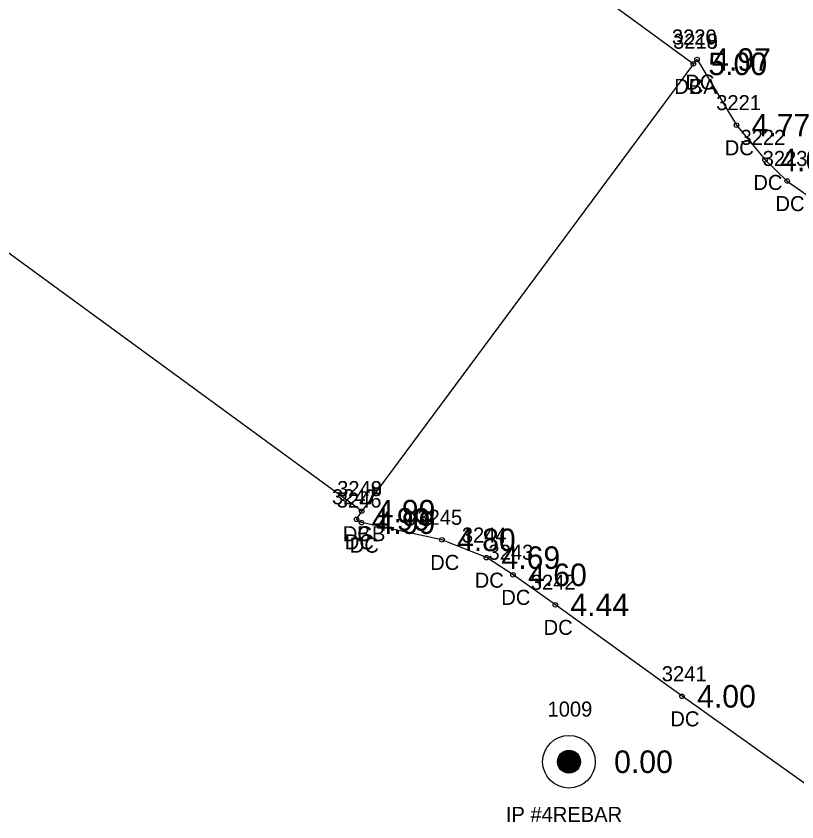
# Model space of a CAD drawing. Extents: x 2608598 to 2610682, y 641451 to 643526.
# Drawn here: x 2609915.7 to 2609967.6, y 641984.1 to 642037.7 of the extents above; entities that cross this region are included whole.
import ezdxf

# ---------------------------------------------------------------- set-up
doc = ezdxf.new("R2010")
doc.units = 0
for name, color, linetype in [('RD_EX_Bldg', 7, 'Continuous'), ('RD_EX_Bldg_txCode', 7, 'Continuous'), ('RD_EX_Conc', 7, 'Continuous'), ('RD_EX_Conc_txCode', 7, 'Continuous'), ('RD_EX_DV_Prop_txCode', 7, 'Continuous'), ('RD_EX_DV_PropPin', 7, 'Continuous'), ('RD_EX_TX_Bldg_ELEV', 7, 'Continuous'), ('RD_EX_TX_Conc_ELEV', 7, 'Continuous'), ('RD_EX_TX_DV_Prop_ELEV', 7, 'Continuous'), ('RD_SMD_Locator', 7, 'Continuous')]:
    doc.layers.add(name, color=color, linetype=linetype)

msp = doc.modelspace()

# ---------------------------------------------------------------- linework, layer by layer
at = {"layer": 'RD_EX_Bldg'}
msp.add_lwpolyline([(2609909.121, 642072.222), (2609960.739, 642034.485), (2609938.692, 642004.745), (2609887.073, 642042.482), (2609909.121, 642072.222)], dxfattribs=at)
at = {"layer": 'RD_EX_Conc'}
for points in [[(2609960.739, 642034.485), (2609960.987, 642034.768), (2609963.606, 642030.403), (2609965.507, 642028.097), (2609966.979, 642026.692), (2609972.604, 642022.767), (2609980.207, 642017.235), (2609987.972, 642011.523)], [(2609969.557, 641985.649), (2609959.989, 641992.436), (2609951.566, 641998.518), (2609948.754, 642000.513), (2609946.984, 642001.655), (2609944.027, 642002.836), (2609938.684, 642003.981), (2609938.35, 642004.199), (2609938.692, 642004.745)]]:
    msp.add_lwpolyline(points, dxfattribs=at)
at = {"layer": 'RD_EX_DV_PropPin'}
for p, q in [((2609951.842, 641987.66), (2609951.842, 641988.513)), ((2609951.877, 641987.612), (2609951.877, 641988.56)), ((2609951.912, 641987.571), (2609951.912, 641988.601)), ((2609951.947, 641987.536), (2609951.947, 641988.637)), ((2609951.982, 641987.504), (2609951.982, 641988.668)), ((2609952.017, 641987.476), (2609952.017, 641988.696)), ((2609952.052, 641987.452), (2609952.052, 641988.721)), ((2609952.087, 641987.43), (2609952.087, 641988.743)), ((2609952.122, 641987.411), (2609952.122, 641988.762)), ((2609952.157, 641987.394), (2609952.157, 641988.779)), ((2609952.192, 641987.379), (2609952.192, 641988.794)), ((2609952.227, 641987.366), (2609952.227, 641988.807)), ((2609952.262, 641987.355), (2609952.262, 641988.818)), ((2609952.297, 641987.346), (2609952.297, 641988.827)), ((2609952.332, 641987.338), (2609952.332, 641988.834)), ((2609952.367, 641987.333), (2609952.367, 641988.84)), ((2609952.402, 641987.329), (2609952.402, 641988.844)), ((2609952.437, 641987.326), (2609952.437, 641988.847)), ((2609952.472, 641987.325), (2609952.472, 641988.847)), ((2609952.507, 641987.326), (2609952.507, 641988.847)), ((2609952.542, 641987.329), (2609952.542, 641988.844)), ((2609952.577, 641987.333), (2609952.577, 641988.84)), ((2609952.612, 641987.338), (2609952.612, 641988.834)), ((2609952.647, 641987.346), (2609952.647, 641988.827)), ((2609952.682, 641987.355), (2609952.682, 641988.818)), ((2609952.717, 641987.366), (2609952.717, 641988.807)), ((2609952.752, 641987.379), (2609952.752, 641988.794)), ((2609952.787, 641987.394), (2609952.787, 641988.779)), ((2609952.822, 641987.411), (2609952.822, 641988.762)), ((2609952.857, 641987.43), (2609952.857, 641988.743)), ((2609952.892, 641987.452), (2609952.892, 641988.721)), ((2609952.927, 641987.476), (2609952.927, 641988.696)), ((2609952.962, 641987.504), (2609952.962, 641988.668)), ((2609952.997, 641987.536), (2609952.997, 641988.637)), ((2609953.032, 641987.571), (2609953.032, 641988.601)), ((2609953.067, 641987.612), (2609953.067, 641988.56)), ((2609953.102, 641987.66), (2609953.102, 641988.513)), ((2609951.737, 641987.89), (2609951.737, 641988.282)), ((2609951.772, 641987.788), (2609951.772, 641988.384)), ((2609951.807, 641987.717), (2609951.807, 641988.456)), ((2609953.137, 641987.717), (2609953.137, 641988.456)), ((2609953.172, 641987.788), (2609953.172, 641988.384)), ((2609953.207, 641987.89), (2609953.207, 641988.282))]:
    msp.add_line(p, q, dxfattribs=at)
for radius in [1.75, 0.761]:
    msp.add_circle((2609952.472, 641988.086), radius, dxfattribs=at)
at = {"layer": 'RD_SMD_Locator'}
for centre in [(2609960.739, 642034.485), (2609960.739, 642034.485), (2609960.987, 642034.768), (2609963.606, 642030.403), (2609965.507, 642028.097), (2609966.979, 642026.692), (2609938.692, 642004.745), (2609938.692, 642004.745), (2609938.35, 642004.199), (2609938.684, 642003.981), (2609944.027, 642002.836), (2609946.984, 642001.655), (2609948.754, 642000.513), (2609951.566, 641998.518), (2609959.989, 641992.436), (2609952.472, 641988.086)]:
    msp.add_circle(centre, 0.15, dxfattribs=at)

# ---------------------------------------------------------------- texts
at = {"layer": 'RD_EX_Bldg_txCode'}
for s, p in [('3218', (2609959.393, 642035.485)), ('B', (2609960.432, 642032.485)), ('3249', (2609937.062, 642005.745)), ('B', (2609938.384, 642002.745))]:
    msp.add_text(s, height=1, dxfattribs=at).set_placement(p)
at = {"layer": 'RD_EX_Conc_txCode'}
for s, p in [('3220', (2609959.318, 642035.768)), ('3219', (2609959.393, 642035.485)), ('DCA', (2609959.472, 642032.485)), ('DC', (2609960.207, 642032.768)), ('3221', (2609962.259, 642031.403)), ('3222', (2609963.877, 642029.097)), ('DC', (2609962.826, 642028.403)), ('3223', (2609965.349, 642027.692)), ('DC', (2609964.728, 642026.097)), ('DC', (2609966.2, 642024.692)), ('3248', (2609937.062, 642005.745)), ('3247', (2609936.72, 642005.199)), ('3246', (2609937.03, 642004.981)), ('3245', (2609942.397, 642003.836)), ('DCB', (2609937.44, 642002.745)), ('3244', (2609945.354, 642002.655)), ('DC', (2609937.571, 642002.199)), ('DC', (2609937.904, 642001.981)), ('3243', (2609947.124, 642001.513)), ('DC', (2609943.248, 642000.836)), ('DC', (2609946.205, 641999.655)), ('3242', (2609949.936, 641999.518)), ('DC', (2609947.974, 641998.513)), ('DC', (2609950.786, 641996.518)), ('3241', (2609958.643, 641993.436)), ('DC', (2609959.21, 641990.436))]:
    msp.add_text(s, height=1, dxfattribs=at).set_placement(p)
at = {"layer": 'RD_EX_DV_Prop_txCode'}
for s, p in [('1009', (2609951.047, 641991.086)), ('IP #4REBAR', (2609948.275, 641984.086))]:
    msp.add_text(s, height=1, dxfattribs=at).set_placement(p)
at = {"layer": 'RD_EX_TX_Bldg_ELEV'}
for s, p in [('5.00', (2609961.739, 642033.735)), ('4.99', (2609939.692, 642003.995))]:
    msp.add_text(s, height=1.5, dxfattribs=at).set_placement(p)
at = {"layer": 'RD_EX_TX_Conc_ELEV'}
for s, p in [('5.00', (2609961.739, 642033.735)), ('4.97', (2609961.987, 642034.018)), ('4.77', (2609964.606, 642029.653)), ('4.68', (2609966.507, 642027.347)), ('4.99', (2609939.692, 642003.995)), ('4.99', (2609939.35, 642003.449)), ('4.99', (2609939.684, 642003.231)), ('4.80', (2609945.027, 642002.086)), ('4.69', (2609947.984, 642000.905)), ('4.60', (2609949.754, 641999.763)), ('4.44', (2609952.566, 641997.768)), ('4.00', (2609960.989, 641991.686))]:
    msp.add_text(s, height=1.5, dxfattribs=at).set_placement(p)
at = {"layer": 'RD_EX_TX_DV_Prop_ELEV'}
msp.add_text('0.00', height=1.5, dxfattribs=at).set_placement((2609955.472, 641987.336))

doc.saveas('drawing.dxf')
